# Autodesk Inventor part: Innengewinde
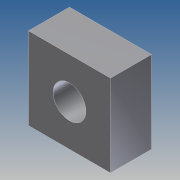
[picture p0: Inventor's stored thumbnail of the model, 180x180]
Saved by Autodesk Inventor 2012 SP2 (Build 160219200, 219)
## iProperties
Company: Caverion Deutschland GmbH - Krantz Komponenten
Created: 2013-10
Part Number: Innengewinde
Material: Standard
Document SubType Name: Modeling
Designer: Wsommer
Density: 1 g/cm^3
Mass: 3.49735 g
Surface Area: 17.508 cm^2
Volume: 3.49735 cm^3
Author: Wsommer
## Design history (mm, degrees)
sketch "Skizze2"
  geometry: L1 (0, 0)-(20, 0); L2 (20, 0)-(20, 20); L3 (20, 20)-(0, 20); L4 (0, 20)-(0, 0); C1 r 4 at (10, 10)
  constraints: 8 end point, 2 parallel, 1 centre point, 1 horizontal, 1 perpendicular
  dimensions: "d0" = 20 distance of L3.end L2.end; "d1" = 20 distance of L2.end L1.end; "d2" = 8 diameter of C1
extrude "Extrusion1" new body sketch "Skizze2" distance "d3" = 10; taper "d4" = 0 deg
node "Volumenkörper1"
node "Volumenkörpern"
node "Oberflächenkörpern"
